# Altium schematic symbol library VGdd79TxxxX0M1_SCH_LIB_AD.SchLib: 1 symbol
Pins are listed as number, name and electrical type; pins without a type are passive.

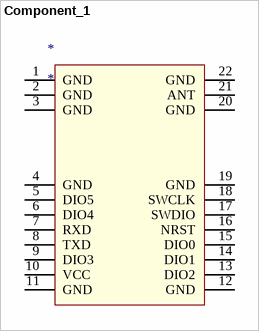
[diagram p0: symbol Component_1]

## Component_1
designator *
pins: 1 GND, 2 GND, 3 GND, 4 GND, 5 DIO5, 6 DIO4, 7 RXD, 8 TXD, 9 DIO3, 10 VCC, 11 GND, 12 GND, 13 DIO2, 14 DIO1, 15 DIO0, 16 NRST, 17 SWDIO, 18 SWCLK, 19 GND, 20 GND, 21 ANT, 22 GND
